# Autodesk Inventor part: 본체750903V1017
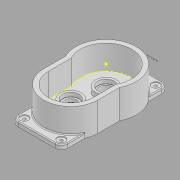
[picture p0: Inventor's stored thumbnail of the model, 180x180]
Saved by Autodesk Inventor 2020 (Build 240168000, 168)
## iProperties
Created: 2025-09
Part Number: 본체750903V1017
Material: 일반
Document SubType Name: Modeling
Designer: 103-1
Density: 1 g/cm^3
Appearance: 기본값
Author: 103-1
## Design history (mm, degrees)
sketch "스케치1"
  geometry: L1 (0, 0)-(0, 154); L2 (0, 0)-(0, -65); L3 (60, 78)-(60, 29.816); L4 (-60, 78)-(-60, 29.816); A1 r 67 centre (0, 0) between (-60, 29.816) and (60, 29.816); A2 r 60 centre (0, 78) between (60, 78) and (-60, 78); 1 further point
  constraints: 8 end point, 4 point on circle, 4 vertical, 2 centre point, 2 coincident, 1 point on line, 1 tangent
  dimensions: "d2" = 154 distance of L1.start L1.end; "d3" = 65 distance of L1.start L2.end; "d6" = 78 distance of L1.start point (0, 78); "d10" = 134 diameter of A1; "d11" = 120 diameter of A2; "d12" = 48.1839 distance of L4.end L4.start
extrude "돌출1" new body sketch "스케치1" distance "d13" = 64; taper "d14" = 0 deg
feature "쉘1" dims "d15" = 10
sketch "스케치2"
  geometry: 1 further point
sketch "스케치3"
  geometry: L1 (-50, 78)-(-50, 27.368) reference; L2 (50, 27.368)-(50, 78) reference; L3 (60, 78)-(60, 29.816) reference; L4 (-60, 29.816)-(-60, 78) reference; L5 (0, 0)-(55, 0); L6 (0, 0)-(-55, 0); L7 (0, 78)-(0, 154); L8 (0, 78)-(0, -83); L9 (0, -83)-(55, -83); L10 (55, -83)-(55, 154); L11 (55, 154)-(-55, 154); L12 (-55, 154)-(-55, -83); L13 (-55, -83)-(0, -83); A1 r 57 centre (0, 0) between (-50, 27.368) and (50, 27.368) reference; A2 r 50 centre (0, 78) between (50, 78) and (-50, 78) reference; A3 r 60 centre (0, 78) between (60, 78) and (-60, 78) reference; A4 r 67 centre (0, 0) between (-60, 29.816) and (60, 29.816) reference; 1 further point
  constraints: 18 end point, 4 perpendicular, 2 horizontal, 2 vertical, 1 point on line
  dimensions: "d16" = 110 distance of L5.end L6.end; "d17" = 76 distance of L7.start L7.end; "d18" = 161 distance of L7.start L8.end
extrude "돌출2" join sketch "스케치3" distance "d19" = 10; taper "d20" = 0 deg
sketch "스케치4"
  geometry: L1 (-55, 14.967)-(-55, -14.967) reference; L2 (-50, -78)-(-50, -27.368) reference; L3 (50, -27.368)-(50, -78) reference; L4 (55, -14.967)-(55, 14.967) reference; A1 r 57 centre (0, 0) between (55, 14.967) and (-55, 14.967) reference; A2 r 57 centre (0, 0) between (-55, -14.967) and (-50, -27.368) reference; A3 r 50 centre (0, -78) between (-50, -78) and (50, -78) reference; A4 r 57 centre (0, 0) between (50, -27.368) and (55, -14.967) reference; 1 further point
  node "투영된 루프2"
sketch "스케치5"
  geometry: C1 r 23.5 at (0, 0); C2 r 23.5 at (0, -78); 2 further points
  constraints: 2 centre point, 2 coincident
  dimensions: "d21" = 47 diameter of C1; "d22" = 47 diameter of C2
extrude "돌출3" join sketch "스케치5" distance "d23" = 12; taper "d24" = 0 deg
sketch "스케치6"
  geometry: C1 r 23.5 at (0, -78); 2 further points
  constraints: 1 centre point, 1 coincident
  dimensions: "d25" = 47 diameter of C1
extrude "돌출4" join sketch "스케치6" distance "d26" = 26; taper "d27" = 0 deg
sketch "스케치7"
  geometry: C1 r 23.5 at (0, 0) reference; 2 further points
  constraints: 1 coincident
hole "구멍1" sketch "스케치7" at (0, 0) diameter "d28" = 30; stored, may be unused: countersink angle "d32" = 90 deg, drill point angle "d34" = 118 deg; dims "d29" = 6, "d30" = 37, "d31" = 9, "d33" = 8
sketch "스케치8"
  geometry: C1 r 23.5 at (0, 0) reference; 2 further points
  constraints: 1 coincident
hole "구멍2" sketch "스케치8" at (0, 0) diameter "d35" = 28; stored, may be unused: countersink angle "d39" = 90 deg, drill point angle "d41" = 118 deg; dims "d36" = 6, "d37" = 37, "d38" = 9, "d40" = 16
sketch "스케치9"
  geometry: 1 further point
sketch "스케치10"
  geometry: 1 further point
chamfer "모따기1" distance "d42" = 0.3; stored, may be unused: second distance "d43" = 2, angle "d44" = 45 deg
fillet "모깎기1" dims "d45" = 0.3
fillet "모깎기2" dims "d46" = 0.3
fillet "모깎기3" dims "d47" = 2
fillet "모깎기4" dims "d48" = 14
sketch "스케치11"
  geometry: A1 r 14 centre (41, 69) between (55, 69) and (41, 83) reference; A2 r 14 centre (-41, 69) between (-41, 83) and (-55, 69) reference; A3 r 14 centre (41, -140) between (41, -154) and (55, -140) reference; A4 r 14 centre (-41, -140) between (-55, -140) and (-41, -154) reference; 5 further points
  constraints: 4 coincident
hole "구멍3" sketch "스케치11" at (41, 69), (-41, 69), (41, -140), (-41, -140) diameter "d49" = 6.6; stored, may be unused: countersink angle "d53" = 90 deg, drill point angle "d55" = 118 deg; dims "d50" = 6, "d51" = 18, "d52" = 2, "d54" = 16
sketch "스케치12"
  geometry: L1 (9.341, 45.489)-(34, 45.489); L2 (34, 45.489)-(34, 41.494); L3 (34, 41.494)-(9.341, 41.494); L4 (9.341, 41.494)-(9.341, 45.489); 1 further point
  constraints: 2 other
sketch "스케치13"
  geometry: 1 further point
node "솔리드1"
node "투영된 루프1"
feature "A9D066F2-1C7D-4E18-AEED-F7BC21143FA4" dims "d28" = 30, "d29" = 6, "d30" = 37, "d31" = 9, "d32" = 90 deg, "d33" = 8, "d34" = 118 deg
